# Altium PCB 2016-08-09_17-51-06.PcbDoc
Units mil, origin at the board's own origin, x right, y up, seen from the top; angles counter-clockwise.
Board outline 2000 x 2000 mil, 4 copper layers (Top Layer, MidLayer1, MidLayer2, Bottom Layer); 20 components, 10 nets, 42 pads, 27 vias.
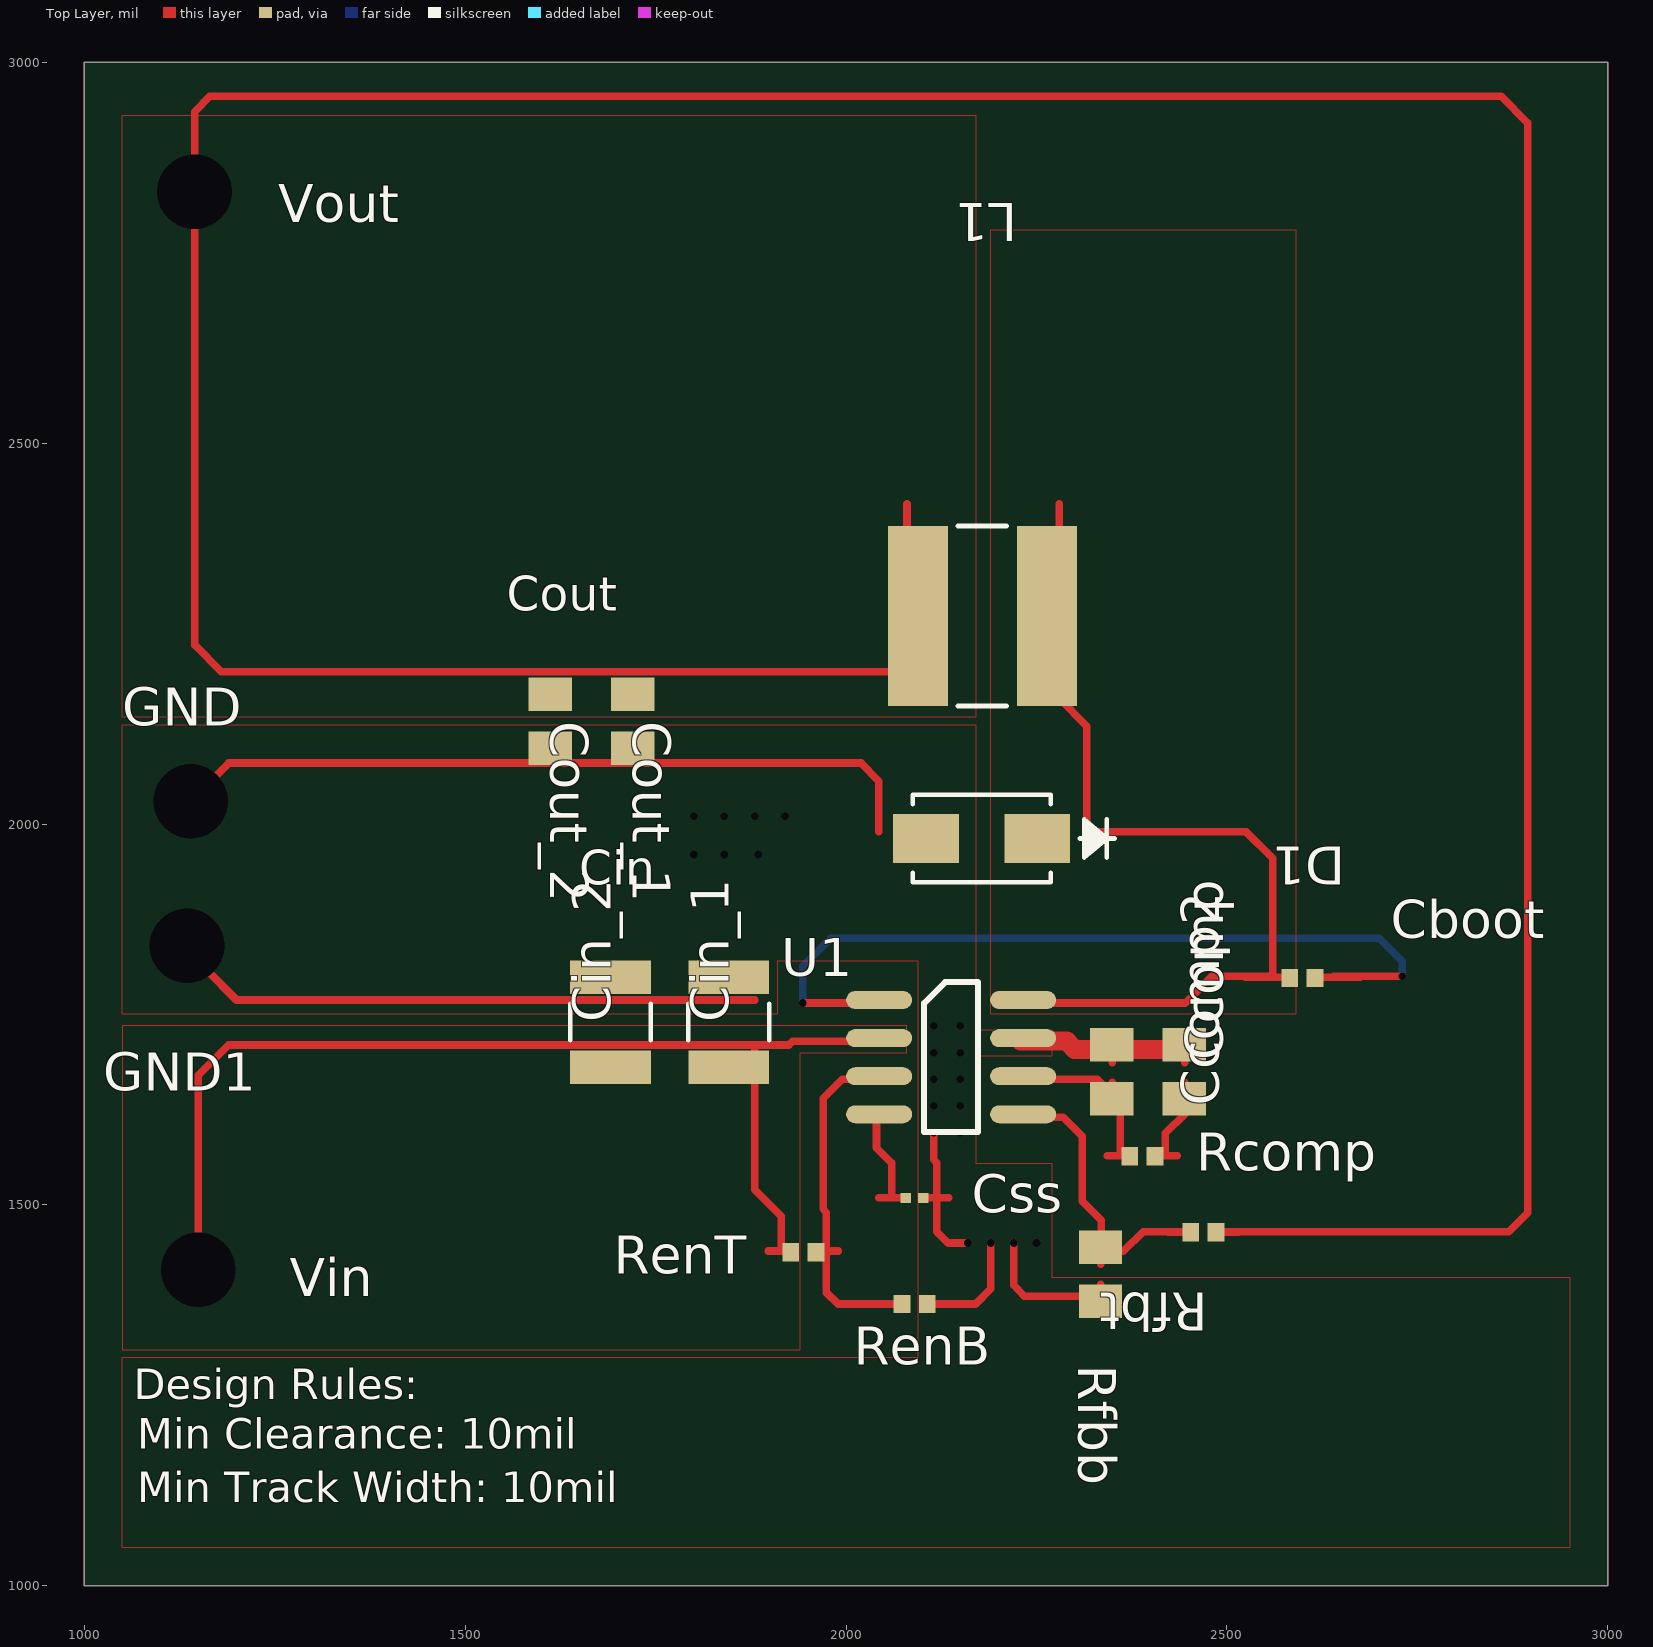
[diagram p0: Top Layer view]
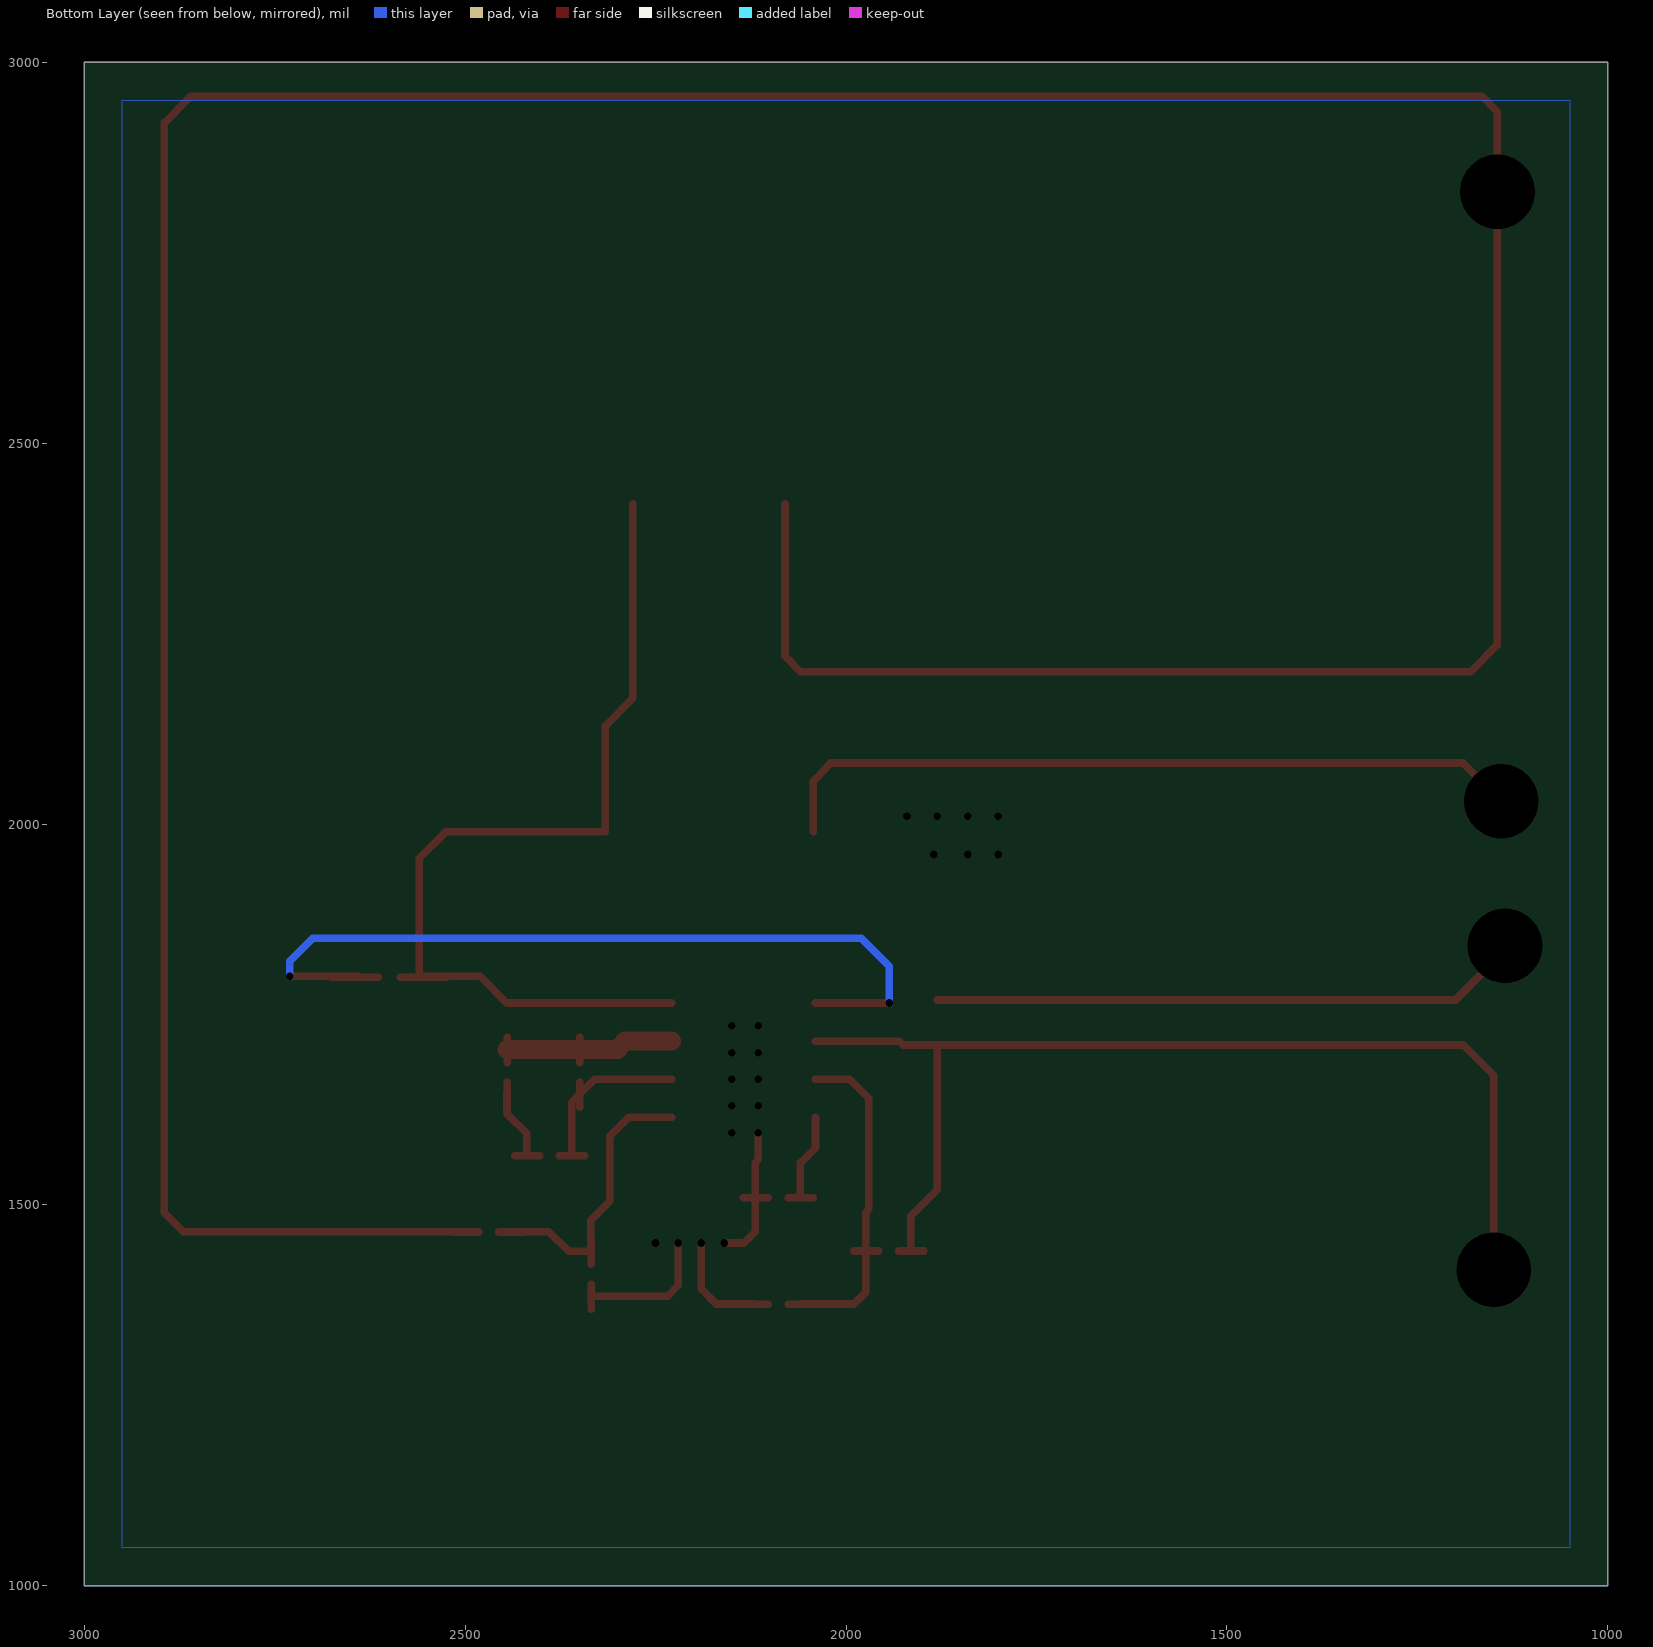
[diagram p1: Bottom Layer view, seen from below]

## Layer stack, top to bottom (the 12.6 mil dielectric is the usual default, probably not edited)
Top Layer: signal copper 1.4
Dielectric: core 12.6, FR-4, Dk 4.8
MidLayer1: signal copper 1.4
Dielectric: prepreg 12.6, FR-4, Dk 4.8
MidLayer2: signal copper 1.4
Dielectric: core 12.6, FR-4, Dk 4.8
Bottom Layer: signal copper 1.4

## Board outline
1000,1000 3000,1000 3000,3000 1000,3000

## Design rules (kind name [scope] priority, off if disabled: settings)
PlaneConnect [All] p0: scope1count=1 scope1_0_kind=Board scope1_0_value=Board scope2count=1 scope2_0_kind=Board scope2_0_value=Board commentlength=0 planeconnectstyle=Direct reliefexpansion=20 reliefentries=4 reliefconductorwidth=10 reliefairgap=10
PlaneConnect [All] p1: planeconnectstyle=Direct reliefexpansion=20 reliefentries=4 reliefconductorwidth=10 reliefairgap=10
PolygonConnect [All] p0: scope1count=1 scope1_0_kind=Board scope1_0_value=Board scope2count=1 scope2_0_kind=Board scope2_0_value=Board commentlength=0 connectstyle=Direct reliefconductorwidth=10 reliefentries=4 polygonreliefangle="90 Angle"
PolygonConnect [All] p1: connectstyle=Direct reliefconductorwidth=10 reliefentries=4 polygonreliefangle="90 Angle"

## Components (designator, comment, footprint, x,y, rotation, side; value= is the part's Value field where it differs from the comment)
Cboot "" 0402 2599,1798 r0 top
Ccomp "" 0805 2444,1675 r90 top
Ccomp2 "" 0805 2349,1675 r90 top
Cin_1 "" 1210 1846,1740 r90 top
Cin_2 "" 1210 1691,1740 r90 top
Cout_1 "" 0805 1720,2135 r270 top
Cout_2 "" 0805 1612,2135 r270 top
Css "" 0201 2090,1509 r0 top
D1 "" SMA 2178,1981 r180 top
GND "" TP-1502 1139,2029 r0 top
GND1 "" TP-1502 1133,1840 r0 top
L1 "" SRN6045 2179,2273 r180 top
Rcomp "" 0402 2389,1564 r0 top
RenB "" 0402 2090,1370 r0 top
RenT "" 0402 1944,1438 r0 top
Rfbb "" 0805 2334,1409 r270 top
Rfbt "" 0402 2469,1464 r180 top
U1 "" D0008A 2138,1694 r0 top
Vin "" TP-1502 1149,1414 r0 top
Vout "" TP-1502 1144,2828 r0 top

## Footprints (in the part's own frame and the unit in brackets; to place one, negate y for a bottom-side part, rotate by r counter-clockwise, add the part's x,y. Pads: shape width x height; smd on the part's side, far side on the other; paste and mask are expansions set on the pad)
0201 [mil]
  rect 14x13 smd: 1(-11.5,0) 2(11.5,0)
0402 [mil]
  rect 22x24 smd: 1(-16.5,0) 2(16.5,0)
0805 [mil]
  rect 44x57 smd: 1(-35.5,0) 2(35.5,0)
1210 [mil]
  rect 44x106 smd: 1(-59,0) 2(59,0)
  silkscreen extent -24,-53 24,53
D0008A [mm]
  oval 2.2x0.6 smd: 1(-2.4,1.905) 2(-2.4,0.635) 3(-2.4,-0.635) 4(-2.4,-1.905) 5(2.4,-1.905) 6(2.4,-0.635) 7(2.4,0.635) 8(2.4,1.905)
  silkscreen extent -0.9,-2.5 0.9,2.5
SMA [mil]
  rect 86x64 smd: 1(-73,0) 2(73,0)
  silkscreen extent -174,-58 90,58
SRN6045 [mm]
  rect 2x6 smd: 1(-2.15,0) 2(2.15,0)
  silkscreen extent -0.82,-3 0.82,3
TP-1502 [mil]
  round 65 / inner round 0 / far side round 65 hole 32: 1(0,0)

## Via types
v1: diameter 0, hole 10, Top Layer to Bottom Layer, 23 vias
v2: diameter 0, hole 98, Top Layer to Bottom Layer, 4 vias

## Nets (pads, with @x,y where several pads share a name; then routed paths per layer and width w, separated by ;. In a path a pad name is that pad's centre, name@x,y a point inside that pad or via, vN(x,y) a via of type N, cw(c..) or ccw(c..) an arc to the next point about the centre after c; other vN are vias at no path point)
0: Ccomp2.2 Ccomp.2 Cin_1.2 Cin_2.2 Cout_1.2 Cout_2.2 Css.2 D1.2 GND1.1 GND.1 RenB.2 Rfbb.2 U1.7 | length 2694.1
  Top Layer w10: GND1.1@1120,1850 1200,1769 1880,1769 ; GND.1@1120,2030 v2(1140,2030) 1190,2080 1690,2080 2020,2080 2043,2056 2043,1990 ; RenB.2@2102,1369.5 2135,1369.5 ; Css.2@2102,1509.5 2135,1509.5 ; v1(2115,1595) 2115,1560 2119,1555 2119,1510 2119,1465 2134,1450 2159,1450 ; 2119,1370 2170,1370 2190,1390 v1(2190,1450) ; v1(2220,1450) 2220,1395 2234,1380 Rfbb.2@2335,1380 ; U1.7@2229,1714 U1.7@2229,1715 ; Rfbb.2@2334.5,1363 2334.5,1396 ; 2349.5,1687 Ccomp2.2@2349.5,1720 ; 2444.5,1687 Ccomp.2@2444.5,1720
  Top Layer w25: U1.7@2229,1715 2290,1715 2300,1704 2350,1704 Ccomp.2@2445,1704
  other v1: 2160,1450 2250,1450 2150,1595 2115,1630 2150,1630 2115,1665 2150,1665 2115,1700 2150,1700 2115,1735 2150,1735 1800,1960 1840,1960 1885,1960 1800,2010 1840,2010 1880,2010 1920,2010
  other v2: 1135,1840
1: RenB.1 RenT.2 U1.3 | length 494.7
  Top Layer w10: RenT.2@1957,1439.5 1990,1439.5 ; U1.3@2040,1665 1995,1665 1970,1640 1970,1495 1974,1490 1974,1440 1974,1385 1990,1370 2060,1370 ; 2043,1369.5 RenB.1@2076,1369.5
2: Ccomp.1 Rcomp.2 | length 156.8
  Top Layer w10: Rcomp.2@2402,1564.5 2435,1564.5 ; 2419,1565 2419,1594 2445,1620 Ccomp.1@2445,1645 ; Ccomp.1@2444.5,1628 Ccomp.1@2444.5,1661
3: Cin_1.1 Cin_2.1 RenT.1 U1.2 Vin.1 | length 1481.1
  Top Layer w10: v2(1150,1415) 1150,1670 1190,1710 1880,1710 ; 1898,1439.5 RenT.1@1931,1439.5 ; 1915,1440 1915,1485 1880,1520 1880,1710 ; U1.2@2040,1715 1930,1715 1925,1710 1880,1710
4: Ccomp2.1 Rcomp.1 U1.6 | length 279.4
  Top Layer w10: U1.6@2229,1665 2330,1665 2350,1645 2360,1635 2360,1565 ; 2343,1564.5 Rcomp.1@2376,1564.5 ; Ccomp2.1@2349.5,1628 Ccomp2.1@2349.5,1661
5: Css.1 U1.4 | length 146.3
  Top Layer w10: U1.4@2040,1615 2040,1575 2060,1555 2060,1510 ; 2043,1509.5 Css.1@2076,1509.5
6: Cboot.2 D1.1 L1.2 U1.8 | length 1264.6
  Top Layer w10: U1.8@2229,1765 2445,1765 2480,1800 2560,1800 2560,1955 2525,1990 2316,1990 2316,2128 2280,2165 2280,2420 ; 2524,1799 2585,1799
7: Rfbb.1 Rfbt.2 U1.5 | length 434.5
  Top Layer w10: U1.5@2229,1615 2285,1615 2310,1590 2310,1505 2335,1480 2335,1439 2364,1439 2390,1465 2440,1465 ; 2334.5,1422 Rfbb.1@2334.5,1455 ; 2423,1464.5 Rfbt.2@2456,1464.5
8: Cboot.1 U1.1 | length 1130.8
  Top Layer w10: v1(1943,1765) U1.1@2040,1765 ; 2614,1799 2675,1799 ; 2640,1800 v1(2730,1800)
  Bottom Layer w10: v1(1943,1765) 1943,1813 1980,1850 2700,1850 2730,1820 v1(2730,1800)
9: Cout_1.1 Cout_2.1 L1.1 Rfbt.1 Vout.1 | length 5499.9
  Top Layer w10: 2080,2420 2080,2220 2060,2200 1690,2200 1180,2200 1145,2235 v2(1145,2830) 1145,2935 1165,2955 2860,2955 2895,2920 2895,1490 2870,1465 2499,1465 ; Rfbt.1@2482,1464.5 2515,1464.5

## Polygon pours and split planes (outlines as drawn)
9 on Top Layer " " (solid, pour order 0): 1050,2930 2170,2930 2170,2140 1050,2140
6 on Top Layer " " (solid, pour order 1): 2190,1750 2190,2780 2590,2780 2590,1750
3 on Top Layer " " (solid, pour order 2): 2080,1735 1050,1735 1050,1310 1940,1310 1940,1700 2080,1700
0 on Top Layer " " (solid, pour order 3): 1050,2130 2170,2130 2170,1730 2270,1730 2270,1695 2170,1695 2170,1555 2270,1555 2270,1405 2950,1405 2950,1050 1050,1050 1050,1300 2095,1300 2095,1820 1910,1820 1910,1750 1050,1750
0 on Bottom Layer " " (solid, pour order 4): 2950,1050 2950,2950 1050,2950 1050,1050

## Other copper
Multi-Layer:
  the board outline again, w1

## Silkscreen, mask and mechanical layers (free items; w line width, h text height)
Top Overlay:
  text "Cout" at 1555,2280 h45
  text "Cin" at 1650,1920 h45
  text "Design Rules:" at 1065,1245 h40
  text "Min Clearance: 10mil" at 1070,1180 h40
  text "Min Track Width: 10mil" at 1070,1110 h40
